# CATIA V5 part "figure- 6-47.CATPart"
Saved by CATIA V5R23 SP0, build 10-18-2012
Part number: Part1
Bounding box of the stored display mesh (mm): x -40 to 40, y -70 to 70.325, z -50 to 50
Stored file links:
  D:\APS\CATIA V5-6R-2013-Project\CATIA V5-6R2013_partfiles\Part_Files\c06_catia_v5-6r2013_prt\figure- 6-47.CATPart
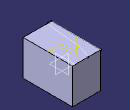
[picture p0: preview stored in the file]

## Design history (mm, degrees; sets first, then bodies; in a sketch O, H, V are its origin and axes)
Body1 (main body)
  Sketch1 on yz-plane, origin (0, 0, 0), H (0, 1, 0), V (0, 0, 1)
    line L1 (70, 50) -> (70, -50)
    line L2 (70, -50) -> (-70, -50)
    line L3 (-70, -50) -> (-70, 50)
    line L4 (-70, 50) -> (70, 50)
    length L1 = 100
    length L4 = 140
    vertical: L1 V, L3 V
    horizontal: L2 H, L4 H
    equidistance: L1 L3 O, L2 L4 O
  Pad1: profile Sketch1, direction (1, 0, 0), length 40, mirrored extent
  Sketch2 on face of Pad1 from Sketch1.L4, origin (0, 0, 50), H (1, 0, 0), V (0, 1, 0)
    spline S1 through (-30.7841, -70) (-23.8817, -36.0861) (-20.1722, 14.4073) (-10.2234, 55.7812) (-3.4223, 70.3253)
    reference projected line E1 (-40, -70) -> (40, -70) from edge [face of Pad1 from Sketch1.L3 | face of Pad1 from Sketch1.L4]
    point P1 (-30.7841, -70)
    coincidence: P1 E1
  Sketch3 on start face of Pad1, origin (-40, 0, 0), H (0, -1, 0), V (0, 0, 1)
    projected line E1 (-70.3253, 50) -> (70, 50) from Sketch2.S1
